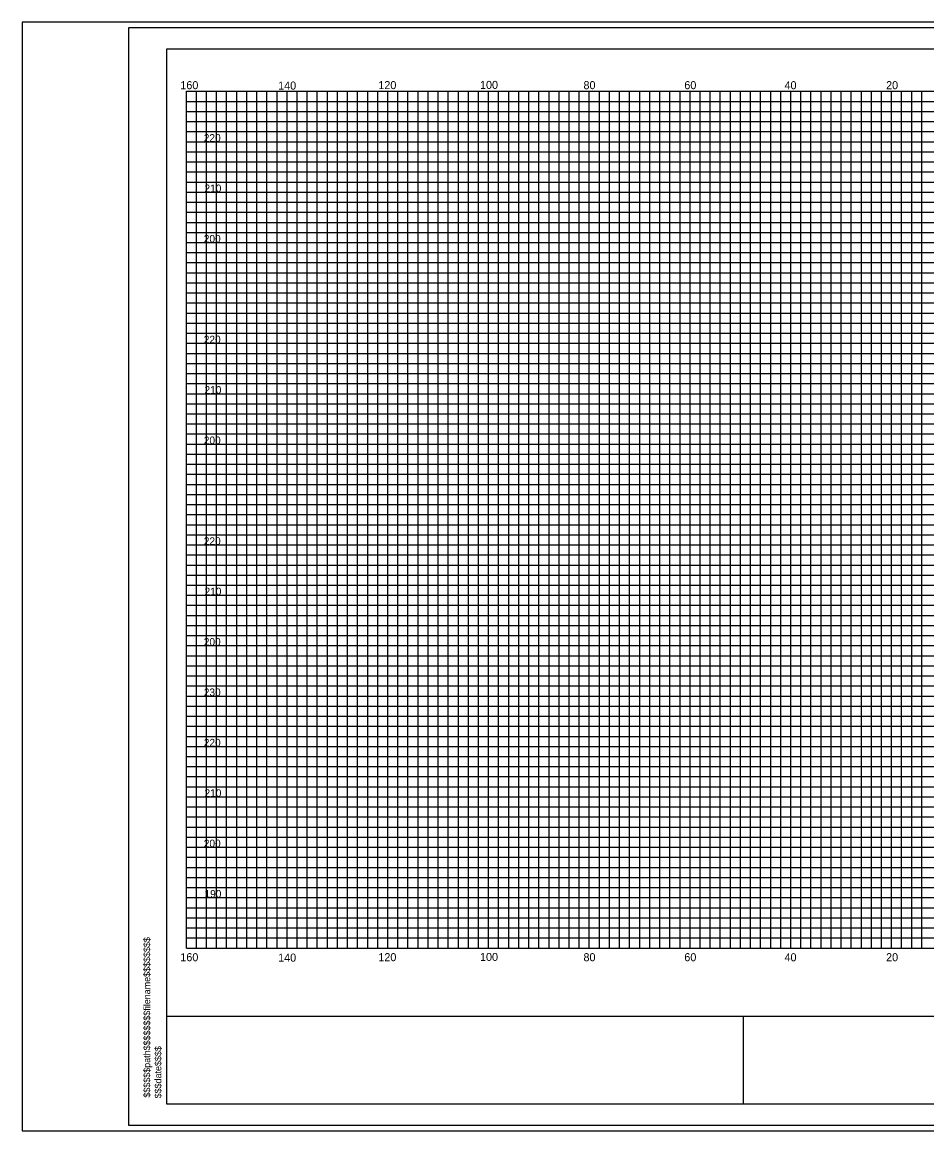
# Model space of a CAD drawing. Extents: x 967 to 1623, y 964 to 7064.
# Drawn here: x 967.4 to 1147, y 4043.7 to 4263.7 of the extents above; entities that cross this region are included whole.
import ezdxf

# ---------------------------------------------------------------- set-up
doc = ezdxf.new("R2010")
doc.units = 0
for name, color, linetype in [('Default', 7, 'Continuous'), ('RD_SHT_Bndy', 7, 'Continuous'), ('RD_SHT_IplotShp', 7, 'Continuous'), ('RD_SHT_MjGrid', 7, 'Continuous'), ('RD_SHT_MnGrid', 7, 'Continuous'), ('RD_SHT_TX', 7, 'Continuous'), ('RD_Sketch1', 7, 'Continuous')]:
    doc.layers.add(name, color=color, linetype=linetype)

msp = doc.modelspace()

# ---------------------------------------------------------------- linework, layer by layer
at = {"layer": 'RD_SHT_Bndy'}
for p, q in [((996.11, 4048.98), (996.11, 4258.46)), ((996.11, 4258.46), (1323.89, 4258.46)), ((996.11, 4066.49), (1323.89, 4066.49)), ((1110.59, 4048.98), (1110.59, 4066.56)), ((1323.89, 4048.98), (996.11, 4048.98))]:
    msp.add_line(p, q, dxfattribs=at)
at = {"layer": 'RD_SHT_IplotShp'}
for points in [[(967.41, 4043.72), (1326.28, 4043.72), (1326.28, 4263.72), (967.41, 4263.72)], [(988.52, 4044.84), (1326.28, 4044.84), (1326.28, 4262.6), (988.52, 4262.6)]]:
    msp.add_lwpolyline(points, close=True, dxfattribs=at)
at = {"layer": 'RD_SHT_MjGrid'}
for p, q in [((1000, 4250), (1320, 4250)), ((1000, 4080), (1000, 4250)), ((1010, 4080), (1010, 4250)), ((1020, 4080), (1020, 4250)), ((1030, 4080), (1030, 4250)), ((1040, 4080), (1040, 4250)), ((1050, 4080), (1050, 4250)), ((1060, 4080), (1060, 4250)), ((1070, 4080), (1070, 4250)), ((1080, 4080), (1080, 4250)), ((1090, 4080), (1090, 4250)), ((1100, 4080), (1100, 4250)), ((1110, 4080), (1110, 4250)), ((1120, 4080), (1120, 4250)), ((1130, 4080), (1130, 4250)), ((1140, 4080), (1140, 4250)), ((1000, 4240), (1320, 4240)), ((1000, 4230), (1320, 4230)), ((1000, 4220), (1320, 4220)), ((1000, 4210), (1320, 4210)), ((1000, 4200), (1320, 4200)), ((1000, 4190), (1320, 4190)), ((1000, 4180), (1320, 4180)), ((1000, 4170), (1320, 4170)), ((1000, 4160), (1320, 4160)), ((1000, 4150), (1320, 4150)), ((1000, 4140), (1320, 4140)), ((1000, 4130), (1320, 4130)), ((1000, 4120), (1320, 4120)), ((1000, 4110), (1320, 4110)), ((1000, 4100), (1320, 4100)), ((1000, 4090), (1320, 4090)), ((1000, 4080), (1320, 4080))]:
    msp.add_line(p, q, dxfattribs=at)
at = {"layer": 'RD_SHT_MnGrid'}
for p, q in [((1002, 4080), (1002, 4250)), ((1004, 4080), (1004, 4250)), ((1006, 4080), (1006, 4250)), ((1008, 4080), (1008, 4250)), ((1012, 4080), (1012, 4250)), ((1014, 4080), (1014, 4250)), ((1016, 4080), (1016, 4250)), ((1018, 4080), (1018, 4250)), ((1022, 4080), (1022, 4250)), ((1024, 4080), (1024, 4250)), ((1026, 4080), (1026, 4250)), ((1028, 4080), (1028, 4250)), ((1032, 4080), (1032, 4250)), ((1034, 4080), (1034, 4250)), ((1036, 4080), (1036, 4250)), ((1038, 4080), (1038, 4250)), ((1042, 4080), (1042, 4250)), ((1044, 4080), (1044, 4250)), ((1046, 4080), (1046, 4250)), ((1048, 4080), (1048, 4250)), ((1052, 4080), (1052, 4250)), ((1054, 4080), (1054, 4250)), ((1056, 4080), (1056, 4250)), ((1058, 4080), (1058, 4250)), ((1062, 4080), (1062, 4250)), ((1064, 4080), (1064, 4250)), ((1066, 4080), (1066, 4250)), ((1068, 4080), (1068, 4250)), ((1072, 4080), (1072, 4250)), ((1074, 4080), (1074, 4250)), ((1076, 4080), (1076, 4250)), ((1078, 4080), (1078, 4250)), ((1082, 4080), (1082, 4250)), ((1084, 4080), (1084, 4250)), ((1086, 4080), (1086, 4250)), ((1088, 4080), (1088, 4250)), ((1092, 4080), (1092, 4250)), ((1094, 4080), (1094, 4250)), ((1096, 4080), (1096, 4250)), ((1098, 4080), (1098, 4250)), ((1102, 4080), (1102, 4250)), ((1104, 4080), (1104, 4250)), ((1106, 4080), (1106, 4250)), ((1108, 4080), (1108, 4250)), ((1112, 4080), (1112, 4250)), ((1114, 4080), (1114, 4250)), ((1116, 4080), (1116, 4250)), ((1118, 4080), (1118, 4250)), ((1122, 4080), (1122, 4250)), ((1124, 4080), (1124, 4250)), ((1126, 4080), (1126, 4250)), ((1128, 4080), (1128, 4250)), ((1132, 4080), (1132, 4250)), ((1134, 4080), (1134, 4250)), ((1136, 4080), (1136, 4250)), ((1138, 4080), (1138, 4250)), ((1142, 4080), (1142, 4250)), ((1144, 4080), (1144, 4250)), ((1146, 4080), (1146, 4250)), ((1000, 4248), (1320, 4248)), ((1000, 4246), (1320, 4246)), ((1000, 4244), (1320, 4244)), ((1000, 4242), (1320, 4242)), ((1000, 4238), (1320, 4238)), ((1000, 4236), (1320, 4236)), ((1000, 4234), (1320, 4234)), ((1000, 4232), (1320, 4232)), ((1000, 4228), (1320, 4228)), ((1000, 4226), (1320, 4226)), ((1000, 4224), (1320, 4224)), ((1000, 4222), (1320, 4222)), ((1000, 4218), (1320, 4218)), ((1000, 4216), (1320, 4216)), ((1000, 4214), (1320, 4214)), ((1000, 4212), (1320, 4212)), ((1000, 4208), (1320, 4208)), ((1000, 4206), (1320, 4206)), ((1000, 4204), (1320, 4204)), ((1000, 4202), (1320, 4202)), ((1000, 4198), (1320, 4198)), ((1000, 4196), (1320, 4196)), ((1000, 4194), (1320, 4194)), ((1000, 4192), (1320, 4192)), ((1000, 4188), (1320, 4188)), ((1000, 4186), (1320, 4186)), ((1000, 4184), (1320, 4184)), ((1000, 4182), (1320, 4182)), ((1000, 4178), (1320, 4178)), ((1000, 4176), (1320, 4176)), ((1000, 4174), (1320, 4174)), ((1000, 4172), (1320, 4172)), ((1000, 4168), (1320, 4168)), ((1000, 4166), (1320, 4166)), ((1000, 4164), (1320, 4164)), ((1000, 4162), (1320, 4162)), ((1000, 4158), (1320, 4158)), ((1000, 4156), (1320, 4156)), ((1000, 4154), (1320, 4154)), ((1000, 4152), (1320, 4152)), ((1000, 4148), (1320, 4148)), ((1000, 4146), (1320, 4146)), ((1000, 4144), (1320, 4144)), ((1000, 4142), (1320, 4142)), ((1000, 4138), (1320, 4138)), ((1000, 4136), (1320, 4136)), ((1000, 4134), (1320, 4134)), ((1000, 4132), (1320, 4132)), ((1000, 4128), (1320, 4128)), ((1000, 4126), (1320, 4126)), ((1000, 4124), (1320, 4124)), ((1000, 4122), (1320, 4122)), ((1000, 4118), (1320, 4118)), ((1000, 4116), (1320, 4116)), ((1000, 4114), (1320, 4114)), ((1000, 4112), (1320, 4112)), ((1000, 4108), (1320, 4108)), ((1000, 4106), (1320, 4106)), ((1000, 4104), (1320, 4104)), ((1000, 4102), (1320, 4102)), ((1000, 4098), (1320, 4098)), ((1000, 4096), (1320, 4096)), ((1000, 4094), (1320, 4094)), ((1000, 4092), (1320, 4092)), ((1000, 4088), (1320, 4088)), ((1000, 4086), (1320, 4086)), ((1000, 4084), (1320, 4084)), ((1000, 4082), (1320, 4082))]:
    msp.add_line(p, q, dxfattribs=at)
at = {"layer": 'RD_Sketch1'}
msp.add_lwpolyline([(967.41, 4043.72), (1326.28, 4043.72), (1326.28, 4263.72), (967.41, 4263.72)], close=True, dxfattribs=at)

# ---------------------------------------------------------------- texts
at = {"layer": 'Default'}
for s, p in [('220', (1003.47, 4240)), ('210', (1003.61, 4230)), ('200', (1003.47, 4220)), ('220', (1003.47, 4200)), ('210', (1003.61, 4190)), ('200', (1003.47, 4180)), ('220', (1003.47, 4160)), ('210', (1003.61, 4150)), ('200', (1003.47, 4140)), ('230', (1003.47, 4130)), ('220', (1003.47, 4120)), ('210', (1003.61, 4110)), ('200', (1003.47, 4100)), ('190', (1003.61, 4090))]:
    msp.add_text(s, height=1.5, dxfattribs=at).set_placement(p)
for s, p in [('$$$$$$path$$$$$$$$filename$$$$$$$$', (992.83, 4050.31)), ('$$$date$$$$', (995.04, 4050.17))]:
    msp.add_text(s, height=1.3258, rotation=90, dxfattribs=at).set_placement(p)
at = {"layer": 'RD_SHT_TX'}
for s, p in [('160', (998.81, 4250.42)), ('140', (1018.23, 4250.34)), ('120', (1038.12, 4250.43)), ('100', (1058.3, 4250.47)), ('80', (1078.84, 4250.42)), ('60', (1098.86, 4250.42)), ('40', (1118.75, 4250.41)), ('20', (1138.91, 4250.42)), ('160', (998.81, 4077.37)), ('140', (1018.23, 4077.29)), ('120', (1038.12, 4077.38)), ('100', (1058.3, 4077.42)), ('80', (1078.84, 4077.37)), ('60', (1098.86, 4077.37)), ('40', (1118.75, 4077.36)), ('20', (1138.91, 4077.37))]:
    msp.add_text(s, height=1.6, dxfattribs=at).set_placement(p)

doc.saveas('drawing.dxf')
